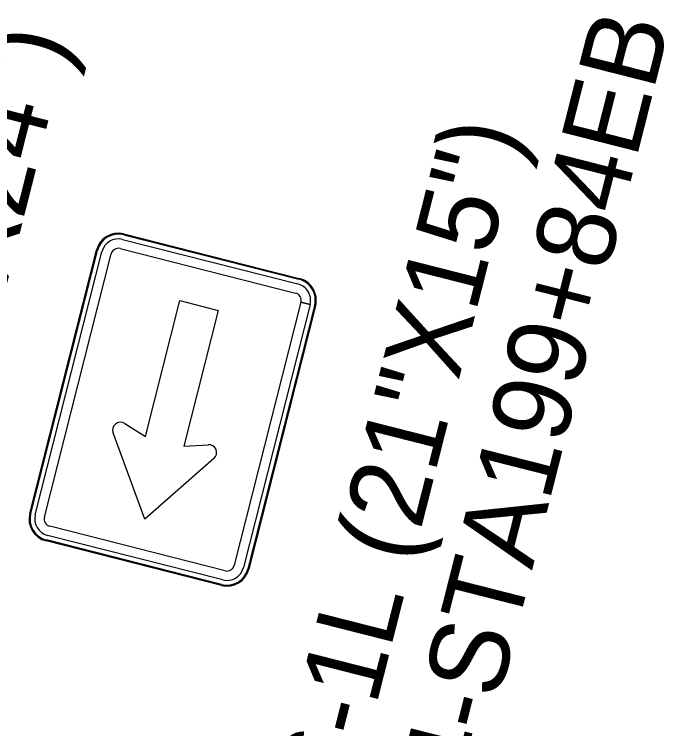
# Model space of a CAD drawing. Extents: x 670257 to 671518, y 737783 to 738188.
# Drawn here: x 670283.048 to 670285.121, y 738174.795 to 738177.068 of the extents above; entities that cross this region are included whole.
import ezdxf

# ---------------------------------------------------------------- set-up
doc = ezdxf.new("R2010")
doc.units = 0
for name, color, linetype in [('Default', 7, 'Continuous'), ('R_SIGN_ANNOT', 7, 'Continuous'), ('R_SIGN_HWY102', 7, 'Continuous')]:
    doc.layers.add(name, color=color, linetype=linetype)

msp = doc.modelspace()

# ---------------------------------------------------------------- linework, layer by layer
at = {"layer": 'R_SIGN_HWY102'}
for p, q in [((670283.3959, 738176.3664), (670283.9538, 738176.225)), ((670283.3959, 738176.3664), (670283.3959, 738176.3664)), ((670283.3966, 738176.3694), (670283.3966, 738176.3694)), ((670283.3966, 738176.3694), (670283.9546, 738176.2279)), ((670283.3966, 738176.3694), (670283.3967, 738176.3694)), ((670283.3967, 738176.3694), (670283.9546, 738176.2279)), ((670283.3922, 738176.3519), (670283.3922, 738176.3519)), ((670283.3922, 738176.3519), (670283.9501, 738176.2104)), ((670283.0969, 738175.4802), (670283.3092, 738176.3173)), ((670283.0969, 738175.4802), (670283.3092, 738176.3173)), ((670283.0998, 738175.4795), (670283.3121, 738176.3166)), ((670283.3092, 738176.3173), (670283.3092, 738176.3173)), ((670283.3092, 738176.3173), (670283.3092, 738176.3173)), ((670283.3121, 738176.3165), (670283.3121, 738176.3166)), ((670283.3849, 738176.3229), (670283.3848, 738176.3228)), ((670283.3849, 738176.3229), (670283.9428, 738176.1814)), ((670283.1144, 738175.4758), (670283.3266, 738176.3129)), ((670283.1434, 738175.4684), (670283.3557, 738176.3055)), ((670283.3266, 738176.3129), (670283.3266, 738176.3129)), ((670283.3557, 738176.3055), (670283.3557, 738176.3055)), ((670283.9538, 738176.2249), (670283.9538, 738176.225)), ((670283.9546, 738176.2279), (670283.9546, 738176.2279)), ((670283.9546, 738176.2279), (670283.9546, 738176.2279)), ((670283.9501, 738176.2104), (670283.9502, 738176.2104)), ((670283.9428, 738176.1813), (670283.9428, 738176.1814)), ((670283.96, 738176.1519), (670283.7478, 738175.3151)), ((670283.9891, 738176.1446), (670283.7769, 738175.3078)), ((670284.0037, 738176.1411), (670283.7914, 738175.3041)), ((670284.0066, 738176.1404), (670283.7943, 738175.3033)), ((670284.0066, 738176.1404), (670283.7943, 738175.3033)), ((670283.96, 738176.1519), (670283.9891, 738176.1446)), ((670283.9892, 738176.1449), (670283.9601, 738176.1522)), ((670283.9601, 738176.1522), (670283.9601, 738176.1522)), ((670283.9892, 738176.1448), (670283.9892, 738176.1449)), ((670284.0066, 738176.1404), (670284.0037, 738176.1412)), ((670284.0037, 738176.1412), (670284.0037, 738176.1411)), ((670284.0037, 738176.1411), (670284.0066, 738176.1404)), ((670284.0066, 738176.1404), (670284.0066, 738176.1404)), ((670283.0969, 738175.4802), (670283.0969, 738175.4802)), ((670283.0969, 738175.4802), (670283.0969, 738175.4802)), ((670283.0998, 738175.4795), (670283.0998, 738175.4795)), ((670283.1143, 738175.4758), (670283.1144, 738175.4758)), ((670283.1434, 738175.4684), (670283.1434, 738175.4684)), ((670283.1607, 738175.4393), (670283.1608, 738175.4393)), ((670283.7187, 738175.2978), (670283.1608, 738175.4393)), ((670283.7113, 738175.2687), (670283.1534, 738175.4102)), ((670283.1534, 738175.4102), (670283.1534, 738175.4102)), ((670283.7069, 738175.2513), (670283.1489, 738175.3928)), ((670283.1489, 738175.3928), (670283.1489, 738175.3928)), ((670283.149, 738175.3928), (670283.1489, 738175.3928)), ((670283.7069, 738175.2513), (670283.149, 738175.3928)), ((670283.1497, 738175.3957), (670283.1497, 738175.3957)), ((670283.7076, 738175.2542), (670283.1497, 738175.3957)), ((670283.7478, 738175.3151), (670283.7478, 738175.3151)), ((670283.7187, 738175.2978), (670283.7187, 738175.2978)), ((670283.7769, 738175.3078), (670283.7769, 738175.3077)), ((670283.7914, 738175.3041), (670283.7914, 738175.3041)), ((670283.7943, 738175.3033), (670283.7943, 738175.3033)), ((670283.7943, 738175.3033), (670283.7943, 738175.3033)), ((670283.7069, 738175.2512), (670283.7069, 738175.2513)), ((670283.7069, 738175.2512), (670283.7069, 738175.2513)), ((670283.7076, 738175.2542), (670283.7076, 738175.2542)), ((670283.7113, 738175.2687), (670283.7113, 738175.2687))]:
    msp.add_line(p, q, dxfattribs=at)
for points in [[(670283.3991, 738175.7663), (670283.4653, 738175.7252), (670283.5748, 738176.1571), (670283.6968, 738176.1261), (670283.5873, 738175.6943), (670283.6651, 738175.6988)], [(670283.3991, 738175.7663), (670283.4653, 738175.7252), (670283.5748, 738176.1571), (670283.6968, 738176.1261), (670283.5873, 738175.6943), (670283.6651, 738175.6988)], [(670283.3991, 738175.7663), (670283.4653, 738175.7252), (670283.5748, 738176.1571), (670283.6968, 738176.1261), (670283.5873, 738175.6943), (670283.6651, 738175.6988)], [(670283.6832, 738175.6548), (670283.4633, 738175.4615), (670283.3622, 738175.7362)], [(670283.6832, 738175.6548), (670283.4633, 738175.4615), (670283.3622, 738175.7362)], [(670283.6832, 738175.6548), (670283.4633, 738175.4615), (670283.3622, 738175.7362)]]:
    msp.add_lwpolyline(points, dxfattribs=at)
for centre, major_axis, start_param, end_param in [((670283.3789, 738176.2996), (-0.0177, -0.0698), 3.141593, 4.712389), ((670283.3789, 738176.2996), (-0.0177, -0.0698), 3.141593, 4.712389), ((670283.3789, 738176.2996), (-0.017, -0.0669), 3.141593, 4.712389), ((670283.3789, 738176.2996), (-0.0133, -0.0523), 3.141593, 4.712389), ((670283.3789, 738176.2996), (-0.0059, -0.0233), 3.141593, 4.712389), ((670283.9369, 738176.1581), (-0.017, -0.0669), 1.570796, 3.141593), ((670283.9369, 738176.1581), (-0.0177, -0.0698), 1.570796, 3.141593), ((670283.9369, 738176.1581), (-0.0177, -0.0698), 1.570796, 3.141593), ((670283.9369, 738176.1581), (-0.0133, -0.0523), 1.570796, 3.141593), ((670283.9369, 738176.1581), (-0.0059, -0.0233), 1.570796, 3.141593), ((670283.3858, 738175.7449), (-0.0062, -0.0244), 2.834398, 5.313642), ((670283.3858, 738175.7449), (-0.0062, -0.0244), 2.834398, 5.313642), ((670283.3858, 738175.7449), (-0.0062, -0.0244), 2.834398, 5.313642), ((670283.6665, 738175.6737), (0.0062, 0.0244), 4.111136, 6.59038), ((670283.6665, 738175.6737), (0.0062, 0.0244), 4.111136, 6.59038), ((670283.6665, 738175.6737), (0.0062, 0.0244), 4.111136, 6.59038), ((670283.1666, 738175.4625), (-0.0177, -0.0698), 4.712389, 6.283185), ((670283.1666, 738175.4625), (-0.0177, -0.0698), 4.712389, 6.283185), ((670283.1666, 738175.4625), (-0.017, -0.0669), 4.712389, 6.283185), ((670283.1666, 738175.4625), (-0.0133, -0.0523), 4.712389, 6.283185), ((670283.1666, 738175.4625), (-0.0059, -0.0233), 4.712389, 6.283185), ((670283.7246, 738175.321), (-0.0059, -0.0233), 0, 1.570796), ((670283.7246, 738175.321), (-0.0177, -0.0698), 0, 1.570796), ((670283.7246, 738175.321), (-0.0177, -0.0698), 0, 1.570796), ((670283.7246, 738175.321), (-0.017, -0.0669), 0, 1.570796), ((670283.7246, 738175.321), (-0.0133, -0.0523), 0, 1.570796)]:
    msp.add_ellipse(centre, major_axis=major_axis, ratio=0.99981, start_param=start_param, end_param=end_param, dxfattribs=at)

# ---------------------------------------------------------------- texts
at = {"layer": 'Default'}
for s, p in [('SS-72-04-STA199+84EB', (670284.216, 738173.4069)), ('M6-1L (21"X15")', (670284.0575, 738174.3072))]:
    msp.add_text(s, height=0.25, rotation=75.7686, dxfattribs=at).set_placement(p)
at = {"layer": 'R_SIGN_ANNOT'}
msp.add_text('M1-1 (24"X24")', height=0.25, rotation=75.7686, dxfattribs=at).set_placement((670282.6623, 738174.7829))

doc.saveas('drawing.dxf')
